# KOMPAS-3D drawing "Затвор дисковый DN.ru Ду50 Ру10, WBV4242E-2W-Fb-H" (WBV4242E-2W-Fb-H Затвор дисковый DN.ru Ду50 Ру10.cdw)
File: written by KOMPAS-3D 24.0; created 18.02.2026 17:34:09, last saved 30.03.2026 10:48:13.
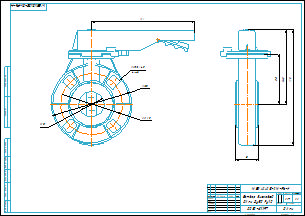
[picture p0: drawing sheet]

Document properties: Автор: R2D2; Форматы листов документа: A2; Полное имя файла: WBV4242E-2W-Fb-H Затвор дисковый DN.ru Ду50 Ру10.m3d; Масса: 1.17; Наименование: Затвор дисковый DN.ru Ду50 Ру10; Количество листов документа: 1; Примечание: D050-81197

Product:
- Part/product: Затвор дисковый DN.ru Ду50 Ру10  | designation WBV4242E-2W-Fb-H
    Масса: 1.17
    Раздел спецификации: Прочие изделия
    Примечание: D050-81197

Referenced files in E:\Работа\Зайцев\Для компаса\: чертеж DN.ru А3.cdt
Referenced files in E:\Работа\Зайцев\WBV4242E-2W-Fb-H Затвор дисковый DN.ru Ду50-200 Ру10\DN50\: WBV4242E-2W-Fb-H Затвор дисковый DN.ru Ду50 Ру10.m3d
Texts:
  чертеж DN.ru А3.cdt
  Затвор дисковый
  DN.ru Ду50 Ру10
  WBV4242E-2W-Fb-H
  Затвор дисковый DN.ru Ду50 Ру10
  WBV4242E-2W-Fb-H Затвор дисковый DN.ru Ду50 Ру10
Dimensions and other numbers on the sheet: 1:1; 0; 1; 2; 1,17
